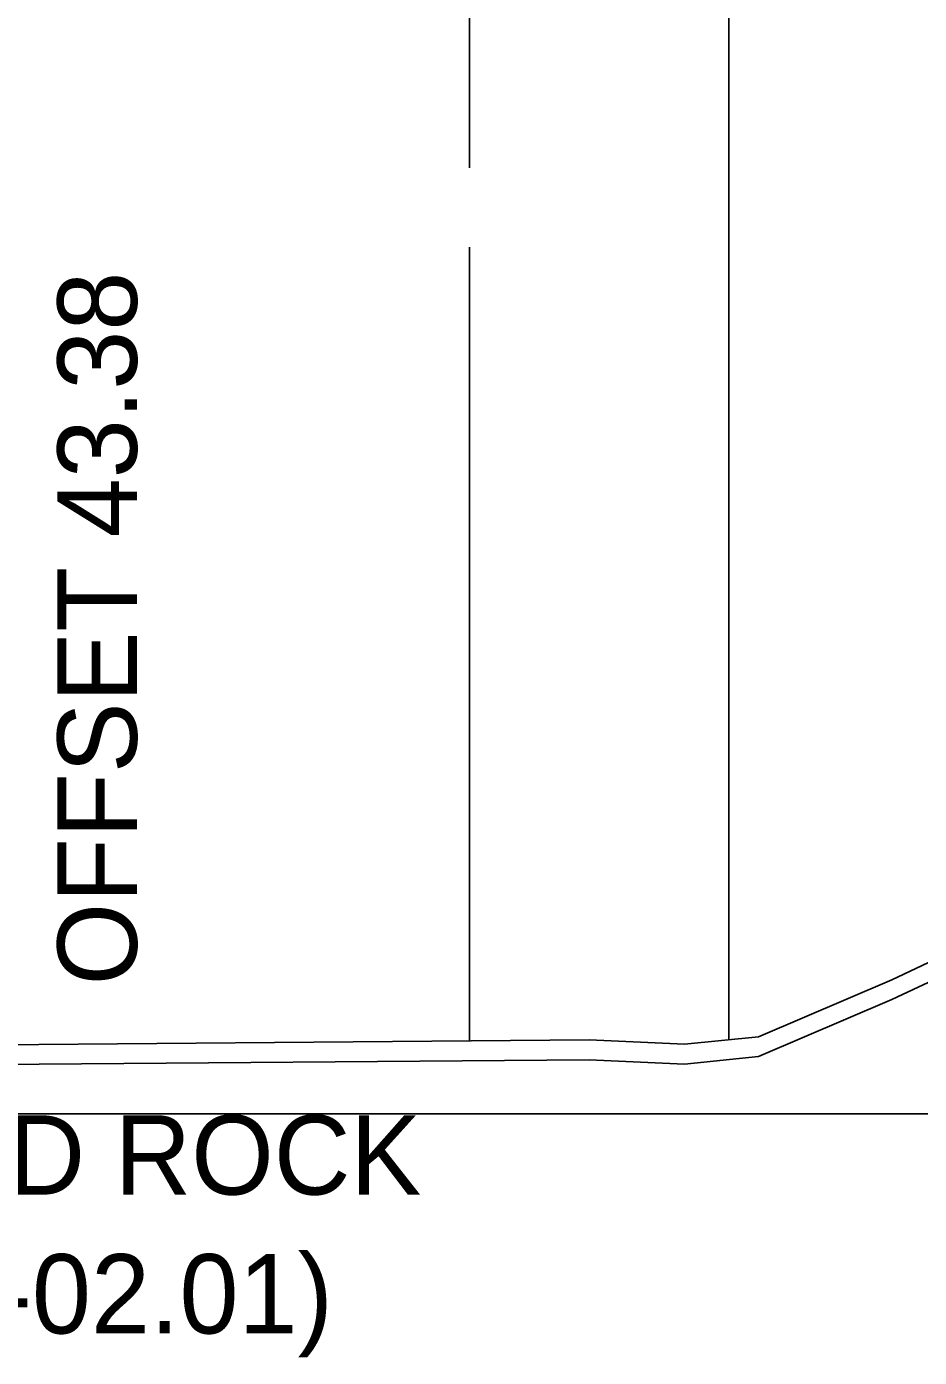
# Model space of a CAD drawing. Extents: x 1574 to 14903, y 7971 to 16537.
# Drawn here: x 14644 to 14655.24, y 8496.93 to 8513.7 of the extents above; entities that cross this region are included whole.
import ezdxf

# ---------------------------------------------------------------- set-up
doc = ezdxf.new("R2010")
doc.units = 0
for name, color, linetype in [('DESIGN - ROW - Right-of-Way Linework', 7, 'Continuous'), ('DESIGN - SHEET - Light Grid', 7, 'Continuous'), ('DESIGN - TYPICAL - Slope Tie Text', 7, 'Continuous'), ('SURVEY - GROUND - Bottom of Topsoil Layer', 7, 'Continuous'), ('SURVEY - GROUND - Top of Ground', 7, 'Continuous'), ('SURVEY - PROPERTY - ROW Lines', 7, 'Continuous')]:
    doc.layers.add(name, color=color, linetype=linetype)

msp = doc.modelspace()

# ---------------------------------------------------------------- linework, layer by layer
at = {"layer": 'DESIGN - ROW - Right-of-Way Linework'}
msp.add_line((14652.84, 8500.935), (14652.84, 8532.935), dxfattribs=at)
at = {"layer": 'DESIGN - SHEET - Light Grid'}
msp.add_line((14600, 8500), (14900, 8500), dxfattribs=at)
at = {"layer": 'SURVEY - GROUND - Bottom of Topsoil Layer'}
for p, q in [((14654.895, 8501.441), (14662.41, 8504.993)), ((14653.214, 8500.723), (14654.895, 8501.441)), ((14642.161, 8500.61), (14651.084, 8500.683)), ((14651.084, 8500.683), (14652.282, 8500.629)), ((14652.282, 8500.629), (14653.214, 8500.723))]:
    msp.add_line(p, q, dxfattribs=at)
at = {"layer": 'SURVEY - GROUND - Top of Ground'}
msp.add_lwpolyline([(14616.951, 8510.241), (14621.92, 8508.475), (14623.638, 8507.904), (14627.888, 8505.735), (14635.553, 8501.765), (14639.329, 8501.174), (14642.161, 8500.86), (14651.084, 8500.933), (14652.282, 8500.879), (14653.214, 8500.973), (14654.895, 8501.691), (14662.41, 8505.243)], dxfattribs=at)
at = {"layer": 'SURVEY - PROPERTY - ROW Lines'}
for p, q in [((14649.576, 8511.921), (14649.576, 8521.921)), ((14649.576, 8500.921), (14649.576, 8510.921))]:
    msp.add_line(p, q, dxfattribs=at)

# ---------------------------------------------------------------- texts
at = {"layer": 'DESIGN - TYPICAL - Slope Tie Text'}
for s, rotation, p in [('OFFSET 43.38', 90, (14645.384, 8501.62)), ('GRADED SOLID ROCK', 360, (14634.626, 8498.984)), ('(ITEM NO. 203-02.01)', 360, (14634.626, 8497.234))]:
    msp.add_text(s, height=1, rotation=rotation, dxfattribs=at).set_placement(p)

doc.saveas('drawing.dxf')
